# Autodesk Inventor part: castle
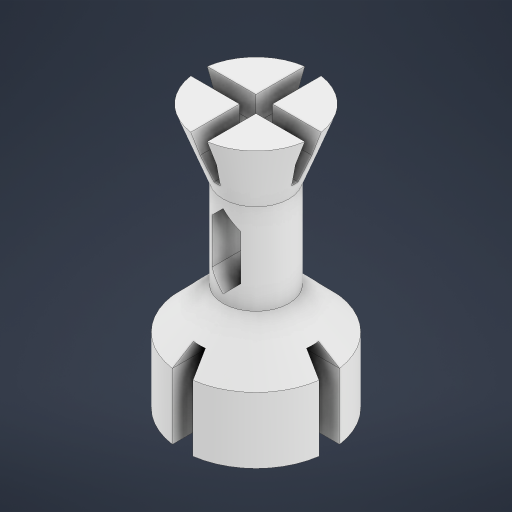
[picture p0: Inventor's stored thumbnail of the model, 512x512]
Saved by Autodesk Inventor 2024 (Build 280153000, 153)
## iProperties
Created: 2025-07
Part Number: castle
Material: ABS Plastic
Document SubType Name: Modeling
Designer: acer
Density: 1.06 g/cm^3
Appearance: Smooth - White
Author: acer
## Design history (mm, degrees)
sketch "Sketch1"
  geometry: L1 (0, 0)-(0, 9); L2 (0, 0)-(32, 0); L3 (0, 9)-(8, 9); L4 (8, 9)-(8, 4); L5 (8, 4)-(24, 4); L6 (32, 0)-(32, 7); L7 (32, 7)-(24, 4)
  constraints: 14 end point, 2 horizontal, 2 perpendicular, 2 vertical
  dimensions: "d0" = 9 distance of L1.start L1.end; "d1" = 32 distance of L1.start L2.end; "d2" = 8 distance of L1.end L3.end; "d3" = 5 distance of L3.end L4.end; "d4" = 16 distance of L4.end L5.end; "d5" = 7 distance of L2.end L6.end
revolve "Revolution1" sketch "Sketch1" stored, may be unused: angle "d6" = 90 deg
chamfer "Chamfer1" distance "d7" = 5; stored, may be unused: second distance "d8" = 2, angle "d9" = 45 deg
sketch "Sketch2"
  geometry: L1 (24, -4)-(24, 4) reference; L2 (40, 1)-(24, 1); L3 (24, 1)-(24, -1); L4 (24, -1)-(40, -1); L5 (40, -1)-(40, 1); L6 (32, -7)-(32, 7) reference; L7 (40, 1)-(24, -1); L8 (24, 1)-(40, -1); L9 (24, -1)-(29, -1); L10 (29, -1)-(24, 0); L11 (24, 0)-(29, 1); 4 further points
  constraints: 18 end point, 4 midpoint, 3 point on line, 2 parallel, 1 horizontal, 1 perpendicular
  dimensions: "d10" = 2 distance of L3.end L2.end; "d11" = 5 distance of L3.end L9.end
extrude "Extrusion1" cut sketch "Sketch2" distance "d12" = 10; taper "d14" = 0 deg; dims "d13" = 11.25, "d15" = 0
chamfer "Chamfer2" distance "d16" = 2; stored, may be unused: second distance "d17" = 2, angle "d18" = 45 deg
sketch "Sketch3"
  geometry: L1 (4, 24)-(-4, 24) reference; L2 (-1, 40)-(1, 40); L3 (1, 40)-(1, 24); L4 (1, 24)-(-1, 24); L5 (-1, 24)-(-1, 40); L6 (6.928, 32)-(-6.928, 32) reference; L7 (-1, 40)-(1, 24); L8 (1, 40)-(-1, 24); L9 (-1, 24)-(-1, 29); L10 (-1, 29)-(0, 24); L11 (0, 24)-(1, 29); L12 (-5.789, 29)-(5.789, 29) reference; 4 further points
  constraints: 18 end point, 4 midpoint, 4 point on line, 2 parallel, 1 horizontal, 1 perpendicular
  dimensions: "d19" = 2 distance of L3.end L4.end; "d20" = 5 distance of L4.end L9.end
extrude "Extrusion2" cut sketch "Sketch3" distance "d21" = 10; taper "d23" = 0 deg; dims "d22" = 11.75, "d24" = 0
chamfer "Chamfer3" distance "d25" = 2; stored, may be unused: second distance "d26" = 2, angle "d27" = 45 deg
sketch "Sketch4"
  geometry: L1 (-4, 13)-(4, 13) reference; L2 (-4, 13)-(-4, 24) reference; L3 (4, 13)-(-4, 13); L4 (-4, 13)-(-4, 24); L5 (-4, 24)-(4, 24); L6 (4, 24)-(4, 13); L7 (4, 13)-(4, 24) reference; L8 (4, 18.5)-(4, 15.75); L9 (4, 15.75)-(-4, 15.75); L10 (4, 18.5)-(4, 21.25); L11 (4, 21.25)-(-4, 21.25); L12 (-1.75, 15.75)-(0, 14); L13 (0, 14)-(1.75, 15.75); L14 (1.75, 21.25)-(0, 23); L15 (0, 23)-(-1.75, 21.25); L16 (-1.75, 21.25)-(-1.75, 15.75); L17 (1.75, 15.75)-(1.75, 21.25); A1 r 1.75 centre (0, 21.25) between (1.75, 21.25) and (0, 23); A2 r 1.75 centre (0, 15.75) between (-1.75, 15.75) and (0, 14); 1 further point
  constraints: 28 end point, 8 point on line, 6 point on circle, 5 perpendicular, 3 midpoint, 3 parallel, 2 centre point, 1 horizontal
  dimensions: "d28" = 2.75 distance of L8.start L8.end; "d29" = 2.75 distance of L8.start L10.end; "d30" = 3.5 diameter of A1; "d31" = 3.5 diameter of A2
extrude "Extrusion3" cut sketch "Sketch4" stored distance "d32" = 10; taper "d33" = 0 deg
sketch "Sketch5"
  geometry: L1 (13, 4)-(13, -4) reference; L2 (-13, 1.25)-(13, 1.25); L3 (13, 1.25)-(13, -1.25); L4 (13, -1.25)-(-13, -1.25); L5 (-13, -1.25)-(-13, 1.25); L6 (-13, 1.25)-(13, -1.25); L7 (13, 1.25)-(-13, -1.25); L8 (13, 0)-(8, 1.25); L9 (8, -9)-(8, 9) reference; L10 (13, 0)-(8, -1.25); 1 further point
  constraints: 16 end point, 5 point on line, 3 midpoint, 2 parallel, 1 horizontal, 1 perpendicular
  dimensions: "d34" = 2.5 distance of L2.end L3.end
extrude "Extrusion4" cut sketch "Sketch5" stored distance "d35" = 30; taper "d36" = 0 deg
chamfer "Chamfer4" distance "d37" = 3; stored, may be unused: second distance "d38" = 2, angle "d39" = 45 deg
sketch "Sketch6"
  geometry: L1 (-4, 13)-(4, 13) reference; L2 (1.25, -13)-(-1.25, -13); L3 (-1.25, -13)-(-1.25, 13); L4 (-1.25, 13)-(1.25, 13); L5 (1.25, 13)-(1.25, -13); L6 (1.25, -13)-(-1.25, 13); L7 (-1.25, -13)-(1.25, 13); L8 (0, 13)-(1.25, 8); L9 (8.913, 8)-(-8.913, 8) reference; L10 (0, 13)-(-1.25, 8); 1 further point
  constraints: 16 end point, 4 point on line, 3 midpoint, 2 parallel, 1 horizontal, 1 perpendicular
  dimensions: "d40" = 2.5 distance of L3.end L4.end
extrude "Extrusion5" cut sketch "Sketch6" stored distance "d41" = 30; taper "d42" = 0 deg
chamfer "Chamfer5" distance "d43" = 3; stored, may be unused: second distance "d44" = 2, angle "d45" = 45 deg
body "Solid1"
